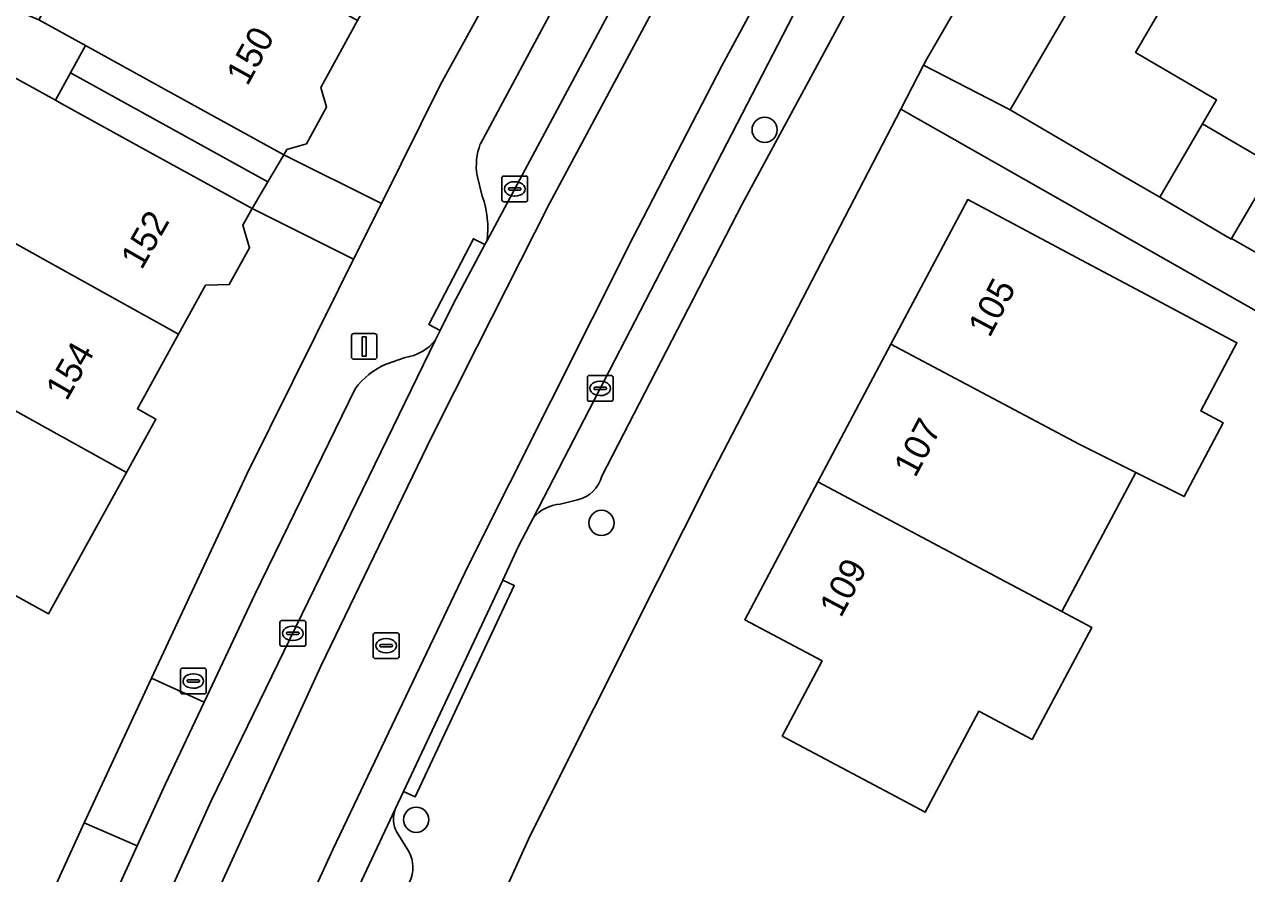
# Model space of a CAD drawing. Extents: x 160349 to 161355, y 381727 to 382854.
# Drawn here: x 160731.24 to 160778.71, y 382109.72 to 382142.68 of the extents above; entities that cross this region are included whole.
import ezdxf

# ---------------------------------------------------------------- set-up
doc = ezdxf.new("R2010")
doc.units = 0
for name, color, linetype in [('IMGEO_Boom', 7, 'Continuous'), ('IMGEO_Brandkraan', 7, 'Continuous'), ('IMGEO_Erf', 7, 'Continuous'), ('IMGEO_Kolk', 7, 'Continuous'), ('IMGEO_Lichtmast', 7, 'Continuous'), ('IMGEO_Pand', 7, 'Continuous'), ('IMGEO_Pand_nummerreeks', 7, 'Continuous'), ('IMGEO_Pand_overbouw', 7, 'Continuous'), ('IMGEO_Parkeervlak_open', 7, 'Continuous'), ('IMGEO_Rijbaan_lokaal_gesloten', 7, 'Continuous'), ('IMGEO_Rioolput', 7, 'Continuous'), ('IMGEO_Voetpad_open', 7, 'Continuous')]:
    doc.layers.add(name, color=color, linetype=linetype)

msp = doc.modelspace()

# ---------------------------------------------------------------- linework, layer by layer
at = {"layer": 'IMGEO_Boom'}
for centre in [(160759.991, 382138.585), (160753.656, 382123.33), (160746.456, 382111.809)]:
    msp.add_circle(centre, 0.489, dxfattribs=at)
at = {"layer": 'IMGEO_Brandkraan'}
for p, q in [((160737.376, 382117.692), (160738.228, 382117.692)), ((160737.301, 382116.766), (160737.301, 382117.618)), ((160737.56, 382117.186), (160737.56, 382117.198)), ((160737.603, 382117.235), (160738.001, 382117.235)), ((160737.789, 382117.472), (160737.814, 382117.472)), ((160738.044, 382117.198), (160738.044, 382117.186)), ((160738.302, 382117.618), (160738.302, 382116.766)), ((160737.998, 382117.149), (160737.6, 382117.149)), ((160737.812, 382116.912), (160737.787, 382116.912)), ((160738.228, 382116.692), (160737.376, 382116.692))]:
    msp.add_line(p, q, dxfattribs=at)
for points in [[(160737.376, 382117.692), (160738.228, 382117.692)], [(160737.301, 382116.766), (160737.301, 382117.618)], [(160738.302, 382117.618), (160738.302, 382116.766)], [(160738.228, 382116.692), (160737.376, 382116.692)]]:
    msp.add_lwpolyline(points, dxfattribs=at)
for centre, radius, start, end in [((160737.378, 382117.616), 0.0765, 91.552, 178.448), ((160737.378, 382117.616), 0.0765, 91.552, 178.448), ((160738.226, 382117.616), 0.0765, 1.552, 88.448), ((160738.226, 382117.616), 0.0765, 1.552, 88.448), ((160737.6, 382117.195), 0.0403, 85.8775, 175.7526), ((160737.597, 382117.185), 0.0366, 178.938, 274.7102), ((160738.001, 382117.192), 0.043, 264.8664, 352.4533), ((160738.005, 382117.197), 0.0386, 1.7309, 96.639), ((160737.378, 382116.768), 0.0765, 181.552, 268.448), ((160737.378, 382116.768), 0.0765, 181.552, 268.448), ((160738.226, 382116.768), 0.0765, 271.552, 358.448), ((160738.226, 382116.768), 0.0765, 271.552, 358.448)]:
    msp.add_arc(centre, radius, start, end, dxfattribs=at)
for centre, major_axis, ratio, start_param, end_param in [((160737.788, 382117.192), (-0.387, 0.002), 0.722429, 4.712389, 7.853982), ((160737.813, 382117.192), (-0.39, 0.002), 0.717154, 1.570796, 4.712389)]:
    msp.add_ellipse(centre, major_axis=major_axis, ratio=ratio, start_param=start_param, end_param=end_param, dxfattribs=at)
at = {"layer": 'IMGEO_Erf'}
for points in [[(160779.322, 382163.825), (160766.279, 382141.32), (160766.166, 382141.102), (160769.524, 382139.361), (160781.775, 382160.346)], [(160781.418, 382146.228), (160778.202, 382148.107), (160774.396, 382141.588), (160777.545, 382139.749), (160776.998, 382138.813), (160779.776, 382137.191), (160778.13, 382134.371), (160782.062, 382132.123)], [(160781.594, 382103.979), (160786.176, 382112.776), (160789.324, 382118.819), (160790.564, 382121.199), (160789.644, 382121.728), (160782.314, 382125.942), (160783.95, 382128.787), (160765.277, 382139.388), (160757.838, 382125.044), (160755.847, 382121.079), (160750.887, 382111.2), (160746.148, 382100.741)], [(160727.159, 382097.684), (160733.561, 382111.687), (160736.181, 382117.303), (160739.877, 382125.223), (160743.443, 382132.387), (160744.029, 382133.564), (160740.081, 382135.529), (160739.73, 382134.892), (160739.985, 382134.011), (160739.196, 382132.58), (160738.278, 382132.562), (160737.231, 382130.662), (160735.63, 382127.756), (160736.344, 382127.362), (160735.201, 382125.288), (160732.176, 382119.797), (160728.662, 382121.734)]]:
    msp.add_lwpolyline(points, dxfattribs=at)
for points in [[(160756.045, 382156.042), (160752.58, 382157.949), (160752.351, 382157.534), (160752.561, 382156.809), (160751.712, 382155.268), (160751.019, 382155.254), (160749.715, 382152.887), (160748.277, 382150.278), (160748.578, 382149.78), (160747.676, 382148.144), (160747.037, 382148.131), (160746.838, 382147.769), (160746.463, 382147.09), (160746.82, 382146.499), (160745.983, 382144.979), (160745.254, 382144.768), (160744.183, 382142.826), (160742.754, 382140.233), (160742.978, 382139.461), (160742.196, 382138.042), (160741.437, 382137.823), (160741.322, 382137.615), (160745.107, 382135.731), (160747.407, 382140.352)], [(160759.216, 382119.571), (160762.058, 382124.921), (160764.897, 382130.266), (160767.878, 382135.879), (160772.294, 382133.534), (160774.614, 382132.302), (160778.337, 382130.325), (160776.93, 382127.676), (160777.804, 382127.211), (160776.285, 382124.352), (160774.406, 382125.288), (160771.536, 382119.886), (160772.694, 382119.271), (160770.381, 382114.921), (160768.308, 382116.023), (160766.227, 382112.109), (160765.09, 382112.707), (160760.674, 382115.053), (160762.225, 382117.973)]]:
    msp.add_lwpolyline(points, close=True, dxfattribs=at)
at = {"layer": 'IMGEO_Kolk'}
for p, q in [((160749.783, 382135.868), (160749.783, 382136.72)), ((160749.858, 382136.794), (160750.71, 382136.794)), ((160750.784, 382136.72), (160750.784, 382135.868)), ((160750.042, 382136.288), (160750.042, 382136.3)), ((160750.48, 382136.251), (160750.082, 382136.251)), ((160750.085, 382136.337), (160750.483, 382136.337)), ((160750.271, 382136.574), (160750.296, 382136.574)), ((160750.526, 382136.3), (160750.526, 382136.288)), ((160750.71, 382135.794), (160749.858, 382135.794)), ((160750.294, 382136.014), (160750.269, 382136.014)), ((160753.18, 382129.052), (160754.032, 382129.052)), ((160753.105, 382128.126), (160753.105, 382128.978)), ((160753.407, 382128.595), (160753.805, 382128.595)), ((160753.593, 382128.832), (160753.618, 382128.832)), ((160754.106, 382128.978), (160754.106, 382128.126)), ((160753.364, 382128.546), (160753.364, 382128.558)), ((160753.802, 382128.509), (160753.404, 382128.509)), ((160753.616, 382128.272), (160753.591, 382128.272)), ((160753.848, 382128.558), (160753.848, 382128.546)), ((160754.032, 382128.052), (160753.18, 382128.052)), ((160741.165, 382118.617), (160741.165, 382119.469)), ((160741.24, 382119.543), (160742.092, 382119.543)), ((160741.467, 382119.086), (160741.865, 382119.086)), ((160741.653, 382119.323), (160741.678, 382119.323)), ((160742.166, 382119.469), (160742.166, 382118.617)), ((160741.424, 382119.037), (160741.424, 382119.049)), ((160741.862, 382119), (160741.464, 382119)), ((160741.676, 382118.763), (160741.651, 382118.763)), ((160741.908, 382119.049), (160741.908, 382119.037)), ((160742.092, 382118.543), (160741.24, 382118.543))]:
    msp.add_line(p, q, dxfattribs=at)
for points in [[(160749.783, 382135.868), (160749.783, 382136.72)], [(160749.858, 382136.794), (160750.71, 382136.794)], [(160750.784, 382136.72), (160750.784, 382135.868)], [(160750.71, 382135.794), (160749.858, 382135.794)], [(160753.18, 382129.052), (160754.032, 382129.052)], [(160753.105, 382128.126), (160753.105, 382128.978)], [(160754.106, 382128.978), (160754.106, 382128.126)], [(160754.032, 382128.052), (160753.18, 382128.052)], [(160741.165, 382118.617), (160741.165, 382119.469)], [(160741.24, 382119.543), (160742.092, 382119.543)], [(160742.166, 382119.469), (160742.166, 382118.617)], [(160742.092, 382118.543), (160741.24, 382118.543)]]:
    msp.add_lwpolyline(points, dxfattribs=at)
for centre, radius, start, end in [((160749.86, 382136.718), 0.0765, 91.552, 178.448), ((160749.86, 382136.718), 0.0765, 91.552, 178.448), ((160750.708, 382136.718), 0.0765, 1.552, 88.448), ((160750.708, 382136.718), 0.0765, 1.552, 88.448), ((160750.082, 382136.297), 0.0403, 85.8775, 175.7526), ((160750.079, 382136.287), 0.0366, 178.938, 274.7102), ((160750.483, 382136.294), 0.043, 264.8664, 352.4533), ((160750.487, 382136.299), 0.0386, 1.7309, 96.639), ((160749.86, 382135.87), 0.0765, 181.552, 268.448), ((160749.86, 382135.87), 0.0765, 181.552, 268.448), ((160750.708, 382135.87), 0.0765, 271.552, 358.448), ((160750.708, 382135.87), 0.0765, 271.552, 358.448), ((160753.182, 382128.976), 0.0765, 91.552, 178.448), ((160753.182, 382128.976), 0.0765, 91.552, 178.448), ((160754.03, 382128.976), 0.0765, 1.552, 88.448), ((160754.03, 382128.976), 0.0765, 1.552, 88.448), ((160753.404, 382128.555), 0.0403, 85.8775, 175.7526), ((160753.809, 382128.557), 0.0386, 1.7309, 96.639), ((160753.182, 382128.128), 0.0765, 181.552, 268.448), ((160753.182, 382128.128), 0.0765, 181.552, 268.448), ((160753.401, 382128.545), 0.0366, 178.938, 274.7102), ((160753.805, 382128.552), 0.043, 264.8664, 352.4533), ((160754.03, 382128.128), 0.0765, 271.552, 358.448), ((160754.03, 382128.128), 0.0765, 271.552, 358.448), ((160741.242, 382119.467), 0.0765, 91.552, 178.448), ((160741.242, 382119.467), 0.0765, 91.552, 178.448), ((160741.464, 382119.046), 0.0403, 85.8775, 175.7526), ((160741.869, 382119.048), 0.0386, 1.7309, 96.639), ((160742.09, 382119.467), 0.0765, 1.552, 88.448), ((160742.09, 382119.467), 0.0765, 1.552, 88.448), ((160741.242, 382118.619), 0.0765, 181.552, 268.448), ((160741.242, 382118.619), 0.0765, 181.552, 268.448), ((160741.461, 382119.036), 0.0366, 178.938, 274.7102), ((160741.865, 382119.043), 0.043, 264.8664, 352.4533), ((160742.09, 382118.619), 0.0765, 271.552, 358.448), ((160742.09, 382118.619), 0.0765, 271.552, 358.448)]:
    msp.add_arc(centre, radius, start, end, dxfattribs=at)
for centre, major_axis, ratio, start_param, end_param in [((160750.27, 382136.294), (-0.387, 0.002), 0.722429, 4.712389, 7.853982), ((160750.295, 382136.294), (-0.39, 0.002), 0.717154, 1.570796, 4.712389), ((160753.592, 382128.552), (-0.387, 0.002), 0.722429, 4.712389, 7.853982), ((160753.617, 382128.552), (-0.39, 0.002), 0.717154, 1.570796, 4.712389), ((160741.652, 382119.043), (-0.387, 0.002), 0.722429, 4.712389, 7.853982), ((160741.677, 382119.043), (-0.39, 0.002), 0.717154, 1.570796, 4.712389)]:
    msp.add_ellipse(centre, major_axis=major_axis, ratio=ratio, start_param=start_param, end_param=end_param, dxfattribs=at)
at = {"layer": 'IMGEO_Lichtmast'}
for p, q in [((160743.942, 382129.779), (160743.942, 382130.579)), ((160743.942, 382130.579), (160743.942, 382129.779)), ((160744.042, 382130.679), (160744.832, 382130.679)), ((160744.832, 382130.679), (160744.042, 382130.679)), ((160744.932, 382130.579), (160744.932, 382129.779)), ((160744.932, 382129.779), (160744.932, 382130.579)), ((160744.832, 382129.679), (160744.042, 382129.679)), ((160744.042, 382129.679), (160744.832, 382129.679))]:
    msp.add_line(p, q, dxfattribs=at)
msp.add_lwpolyline([(160744.362, 382130.554), (160744.512, 382130.554), (160744.512, 382129.804), (160744.362, 382129.804), (160744.362, 382130.554)], dxfattribs=at)
for centre, start, end in [((160744.042, 382130.579), 90, 180), ((160744.042, 382130.579), 90, 180), ((160744.832, 382130.579), 0, 90), ((160744.832, 382130.579), 360, 90), ((160744.042, 382129.779), 180, 270), ((160744.042, 382129.779), 180, 270), ((160744.832, 382129.779), 270, 0), ((160744.832, 382129.779), 270, 0)]:
    msp.add_arc(centre, 0.1, start, end, dxfattribs=at)
at = {"layer": 'IMGEO_Pand'}
for points in [[(160787.375, 382156.487), (160787.631, 382156.928), (160781.775, 382160.346), (160769.524, 382139.361), (160773.842, 382136.84), (160775.336, 382135.968), (160776.998, 382138.813), (160777.545, 382139.749), (160774.396, 382141.588), (160778.202, 382148.107), (160781.418, 382146.228)], [(160744.183, 382142.826), (160733.028, 382149.005), (160731.611, 382146.432), (160732.105, 382145.967), (160733.19, 382145.369), (160731.806, 382142.859), (160733.617, 382141.861), (160736.943, 382140.028), (160741.322, 382137.615), (160741.437, 382137.823), (160742.196, 382138.042), (160742.978, 382139.461), (160742.754, 382140.233)], [(160726.516, 382136.595), (160737.231, 382130.662), (160738.278, 382132.562), (160739.196, 382132.58), (160739.985, 382134.011), (160739.73, 382134.892), (160740.081, 382135.529), (160735.702, 382137.942), (160732.701, 382139.595), (160732.446, 382139.736), (160730.575, 382140.767), (160729.205, 382138.281), (160727.856, 382139.025)], [(160776.998, 382138.813), (160775.336, 382135.968), (160778.116, 382134.346), (160778.13, 382134.371), (160779.776, 382137.191)], [(160725.115, 382130.874), (160735.201, 382125.288), (160736.344, 382127.362), (160735.63, 382127.756), (160737.231, 382130.662), (160726.516, 382136.595), (160725.078, 382133.985), (160726.506, 382133.198)], [(160774.614, 382132.302), (160772.294, 382133.534), (160767.878, 382135.879), (160764.897, 382130.266), (160772.203, 382126.386), (160774.406, 382125.288), (160776.285, 382124.352), (160777.804, 382127.211), (160776.93, 382127.676), (160778.337, 382130.325)], [(160725.115, 382130.874), (160723.647, 382128.423), (160722.011, 382129.049), (160720.671, 382126.617), (160723.702, 382124.947), (160723.508, 382124.575), (160727.797, 382122.21), (160728.662, 382121.734), (160732.176, 382119.797), (160735.201, 382125.288)], [(160772.203, 382126.386), (160764.897, 382130.266), (160762.058, 382124.921), (160769.363, 382121.04), (160771.536, 382119.886), (160774.406, 382125.288)], [(160772.694, 382119.271), (160771.536, 382119.886), (160769.363, 382121.04), (160762.058, 382124.921), (160759.216, 382119.571), (160762.225, 382117.973), (160760.674, 382115.053), (160765.09, 382112.707), (160766.227, 382112.109), (160768.308, 382116.023), (160770.381, 382114.921)]]:
    msp.add_lwpolyline(points, close=True, dxfattribs=at)
at = {"layer": 'IMGEO_Pand_overbouw'}
for points in [[(160741.322, 382137.615), (160736.943, 382140.028), (160733.617, 382141.861), (160733.032, 382140.799), (160740.702, 382136.572)], [(160740.081, 382135.529), (160740.702, 382136.572), (160733.032, 382140.799), (160732.446, 382139.736), (160732.701, 382139.595), (160735.702, 382137.942)]]:
    msp.add_lwpolyline(points, close=True, dxfattribs=at)
at = {"layer": 'IMGEO_Parkeervlak_open'}
for points in [[(160773.923, 382165.502), (160769.521, 382158.198), (160761.102, 382143.043), (160750.999, 382123.515)], [(160753.669, 382125.15), (160759.119, 382135.702), (160763.68, 382144.133), (160768.038, 382151.929), (160773.792, 382161.972)], [(160749.208, 382134.286), (160755.174, 382145.412), (160760.107, 382154.484)], [(160756.864, 382152.793), (160748.949, 382138.039)], [(160748.822, 382136.82), (160749.025, 382136.008)], [(160704.223, 382028.902), (160705.42, 382031.515), (160711.373, 382047.241), (160717.39, 382062.79), (160724.098, 382079.993), (160731.504, 382097.136), (160738.5, 382112.538), (160747.213, 382130.437)], [(160746.026, 382129.748), (160745.29, 382129.494)], [(160744.083, 382128.529), (160740.196, 382120.555), (160738.22, 382116.368), (160736.727, 382113.204), (160735.627, 382110.796), (160733.119, 382105.306), (160729.265, 382096.815), (160729.027, 382096.291), (160726.382, 382090.148), (160724.822, 382086.526), (160720.616, 382076.203), (160716.296, 382065.22), (160710.641, 382050.478), (160703.919, 382032.385)], [(160752.056, 382124.058), (160752.729, 382124.223)], [(160745.645, 382112.221), (160744.243, 382109.241), (160738.037, 382095.914), (160731.709, 382081.366), (160726.166, 382067.458), (160723.26, 382059.82)], [(160746.173, 382110.574), (160745.704, 382111.323)]]:
    msp.add_lwpolyline(points, dxfattribs=at)
for centre, radius, start, end in [((160751.152, 382137.193), 2.36, 159.0024, 189.102), ((160745.552, 382134.768), 3.688, 352.4867, 19.6456), ((160745.75, 382131.59), 1.862, 278.5112, 321.7552), ((160746.437, 382126.822), 2.907, 113.2294, 144.0554), ((160752.426, 382125.47), 1.283, 283.6441, 345.558), ((160752.161, 382122.552), 1.509, 94.0075, 140.3732), ((160746.649, 382111.836), 1.075, 159.0198, 208.4982), ((160745.051, 382109.959), 1.279, 333.7099, 28.7154)]:
    msp.add_arc(centre, radius, start, end, dxfattribs=at)
at = {"layer": 'IMGEO_Rijbaan_lokaal_gesloten'}
for points in [[(160812.989, 382240.37), (160784.239, 382192.537), (160777.906, 382181.828), (160776.425, 382182.776), (160776.168, 382182.334), (160769.164, 382170.249), (160770.494, 382169.628), (160766.428, 382162.546), (160760.731, 382152.677), (160755.42, 382142.776), (160751.633, 382135.727), (160748.813, 382130.153), (160747.076, 382126.71), (160742.756, 382117.768), (160731.871, 382093.997), (160727.444, 382083.882), (160724.887, 382077.653), (160720.494, 382066.374), (160710.123, 382039.204), (160704.275, 382025.25)], [(160696.524, 381990.659), (160696.749, 381990.258), (160698.267, 381993.805), (160702.724, 382005.472), (160701.297, 382006.186), (160706.444, 382018.907), (160712.871, 382036.35), (160718.969, 382052.415), (160728.018, 382076.284), (160733.461, 382089.005), (160737.526, 382098.251), (160743.231, 382110.677), (160748.477, 382121.661), (160754.903, 382134.448), (160758.33, 382141.071), (160759.953, 382144.071), (160767.084, 382156.956), (160773.018, 382167.169), (160774.485, 382166.436), (160782.592, 382179.909), (160781.379, 382180.62), (160792.985, 382200.423)], [(160731.871, 382093.997), (160742.756, 382117.768), (160747.076, 382126.71), (160748.813, 382130.153), (160751.633, 382135.727), (160755.42, 382142.776), (160760.731, 382152.677), (160766.428, 382162.546), (160770.494, 382169.628)], [(160768.528, 382169.151), (160768.313, 382168.781), (160762.651, 382159.028), (160762.421, 382158.632), (160761.503, 382157.051), (160760.224, 382154.7), (160760.107, 382154.484), (160755.174, 382145.412), (160749.208, 382134.286), (160749.125, 382134.13), (160747.889, 382131.825), (160747.391, 382130.802), (160747.213, 382130.437), (160738.5, 382112.538), (160731.504, 382097.136)], [(160744.243, 382109.241), (160745.645, 382112.221), (160745.963, 382112.904), (160749.817, 382121.109), (160750.437, 382122.429), (160750.999, 382123.515), (160761.102, 382143.043), (160769.521, 382158.198), (160773.923, 382165.502), (160774.219, 382165.994), (160774.485, 382166.436), (160773.018, 382167.169), (160767.084, 382156.956), (160759.953, 382144.071), (160758.33, 382141.071), (160754.903, 382134.448), (160748.477, 382121.661), (160743.231, 382110.677), (160737.526, 382098.251)]]:
    msp.add_lwpolyline(points, dxfattribs=at)
at = {"layer": 'IMGEO_Rioolput'}
for p, q in [((160744.792, 382118.14), (160744.792, 382118.992)), ((160744.867, 382119.066), (160745.719, 382119.066)), ((160745.094, 382118.609), (160745.492, 382118.609)), ((160745.28, 382118.846), (160745.305, 382118.846)), ((160745.793, 382118.992), (160745.793, 382118.14)), ((160745.051, 382118.56), (160745.051, 382118.572)), ((160745.489, 382118.523), (160745.091, 382118.523)), ((160745.303, 382118.286), (160745.278, 382118.286)), ((160745.535, 382118.572), (160745.535, 382118.56)), ((160745.719, 382118.066), (160744.867, 382118.066))]:
    msp.add_line(p, q, dxfattribs=at)
for points in [[(160744.792, 382118.14), (160744.792, 382118.992)], [(160744.867, 382119.066), (160745.719, 382119.066)], [(160745.793, 382118.992), (160745.793, 382118.14)], [(160745.719, 382118.066), (160744.867, 382118.066)]]:
    msp.add_lwpolyline(points, dxfattribs=at)
for centre, radius, start, end in [((160744.869, 382118.99), 0.0765, 91.552, 178.448), ((160744.869, 382118.99), 0.0765, 91.552, 178.448), ((160745.091, 382118.569), 0.0403, 85.8775, 175.7526), ((160745.496, 382118.571), 0.0386, 1.7309, 96.639), ((160745.717, 382118.99), 0.0765, 1.552, 88.448), ((160745.717, 382118.99), 0.0765, 1.552, 88.448), ((160744.869, 382118.142), 0.0765, 181.552, 268.448), ((160744.869, 382118.142), 0.0765, 181.552, 268.448), ((160745.088, 382118.559), 0.0366, 178.938, 274.7102), ((160745.492, 382118.566), 0.043, 264.8664, 352.4533), ((160745.717, 382118.142), 0.0765, 271.552, 358.448), ((160745.717, 382118.142), 0.0765, 271.552, 358.448)]:
    msp.add_arc(centre, radius, start, end, dxfattribs=at)
for centre, major_axis, ratio, start_param, end_param in [((160745.279, 382118.566), (-0.387, 0.002), 0.722429, 4.712389, 7.853982), ((160745.304, 382118.566), (-0.39, 0.002), 0.717154, 1.570796, 4.712389)]:
    msp.add_ellipse(centre, major_axis=major_axis, ratio=ratio, start_param=start_param, end_param=end_param, dxfattribs=at)
at = {"layer": 'IMGEO_Voetpad_open'}
for points in [[(160767.703, 382175.981), (160765.349, 382171.856), (160758.992, 382160.743), (160756.826, 382157.451), (160756.792, 382157.399), (160756.045, 382156.042), (160747.407, 382140.352), (160745.107, 382135.731), (160744.029, 382133.564), (160743.443, 382132.387), (160739.877, 382125.223), (160736.181, 382117.303), (160738.22, 382116.368), (160740.196, 382120.555), (160744.083, 382128.529)], [(160705.658, 382002.985), (160707.027, 382005.872), (160723.769, 382047.981), (160723.909, 382047.851), (160734.483, 382073.75), (160746.148, 382100.741), (160750.887, 382111.2), (160755.847, 382121.079), (160757.838, 382125.044), (160765.277, 382139.388), (160766.166, 382141.102), (160766.279, 382141.32), (160779.322, 382163.825)], [(160773.792, 382161.972), (160768.038, 382151.929), (160763.68, 382144.133), (160759.119, 382135.702), (160753.669, 382125.15)], [(160748.949, 382138.039), (160756.864, 382152.793)], [(160730.575, 382140.767), (160732.446, 382139.736), (160732.701, 382139.595), (160735.702, 382137.942), (160740.081, 382135.529), (160744.029, 382133.564), (160745.107, 382135.731), (160741.322, 382137.615), (160736.943, 382140.028), (160733.617, 382141.861), (160731.806, 382142.859), (160724.121, 382146.12)], [(160749.025, 382136.008), (160748.822, 382136.82)], [(160747.213, 382130.437), (160747.391, 382130.802), (160746.948, 382131.033), (160748.682, 382134.361), (160749.125, 382134.13), (160749.208, 382134.286)], [(160745.29, 382129.494), (160746.026, 382129.748)], [(160752.729, 382124.223), (160752.056, 382124.058)], [(160750.999, 382123.515), (160750.437, 382122.429), (160749.817, 382121.109), (160750.269, 382120.897), (160746.415, 382112.692), (160745.963, 382112.904), (160745.645, 382112.221)], [(160745.704, 382111.323), (160746.173, 382110.574)]]:
    msp.add_lwpolyline(points, dxfattribs=at)
for points in [[(160775.336, 382135.968), (160773.842, 382136.84), (160769.524, 382139.361), (160766.166, 382141.102), (160765.277, 382139.388), (160783.95, 382128.787), (160784.855, 382130.356), (160781.989, 382131.996), (160782.062, 382132.123), (160778.13, 382134.371), (160778.116, 382134.346)], [(160749.125, 382134.13), (160748.682, 382134.361), (160746.948, 382131.033), (160747.391, 382130.802), (160747.889, 382131.825)], [(160749.817, 382121.109), (160745.963, 382112.904), (160746.415, 382112.692), (160750.269, 382120.897)], [(160736.181, 382117.303), (160733.561, 382111.687), (160735.627, 382110.796), (160736.727, 382113.204), (160738.22, 382116.368)], [(160727.159, 382097.684), (160729.265, 382096.815), (160733.119, 382105.306), (160735.627, 382110.796), (160733.561, 382111.687)]]:
    msp.add_lwpolyline(points, close=True, dxfattribs=at)
for centre, radius, start, end in [((160751.152, 382137.193), 2.36, 159.0024, 189.102), ((160745.552, 382134.768), 3.688, 352.4867, 19.6456), ((160745.75, 382131.59), 1.862, 278.5112, 321.7552), ((160746.437, 382126.822), 2.907, 113.2294, 144.0554), ((160752.426, 382125.47), 1.283, 283.6441, 345.558), ((160752.161, 382122.552), 1.509, 94.0075, 140.3732), ((160746.649, 382111.836), 1.075, 159.0198, 208.4982), ((160745.051, 382109.959), 1.279, 333.7099, 28.7154)]:
    msp.add_arc(centre, radius, start, end, dxfattribs=at)

# ---------------------------------------------------------------- texts
at = {"layer": 'IMGEO_Pand_nummerreeks'}
for s, rotation, p in [('150', 61.0287, (160739.902, 382140.255)), ('152', 60.2035, (160735.796, 382133.118)), ('105', 62.0227, (160768.727, 382130.486)), ('154', 60.2035, (160732.882, 382128.029)), ('107', 62.0227, (160765.84, 382125.05)), ('109', 62.0227, (160762.953, 382119.614))]:
    msp.add_text(s, height=1, rotation=rotation, dxfattribs=at).set_placement(p)

doc.saveas('drawing.dxf')
